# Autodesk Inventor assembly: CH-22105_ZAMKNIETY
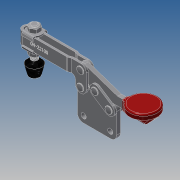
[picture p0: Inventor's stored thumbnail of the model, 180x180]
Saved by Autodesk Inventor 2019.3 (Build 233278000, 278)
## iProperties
Company: Microsoft
Created: 2017-06
Part Number: CH-22105_ZAMKNIETY
Material: Ogólny
Description: STEP AP203
Document SubType Name: Assembly
Designer: CADENGINEERING4
Sending System: SolidWorks 2015
Preprocessor: SwSTEP 2.0
Title: CH-22105.STEP
Author: Windows
Revision Number: ÈÎºÎ
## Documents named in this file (9)
- E:\STRONA\Horizontal toggle clamp\CH-22105\CH-22105_ZAMKNIETY.iam
- E:\STRONA\Horizontal toggle clamp\CH-22105\22105-01.ipt
- E:\STRONA\Horizontal toggle clamp\CH-22105\14134.ipt
- E:\STRONA\Horizontal toggle clamp\CH-22105\14134-02.ipt
- E:\STRONA\Horizontal toggle clamp\CH-22105\22105-02.ipt
- E:\STRONA\Horizontal toggle clamp\CH-22105\22105-03.ipt
- E:\STRONA\Horizontal toggle clamp\CH-22105\22105-04.ipt
- E:\STRONA\Horizontal toggle clamp\CH-22105\FW140.ipt
- E:\STRONA\Horizontal toggle clamp\CH-22105\22105-05.ipt
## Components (14 placed, 14 different names)
1. 22105-01_1
2. 14134_2
3. 14134-02_3
4. 22105-02_4
5. 22105-03_5
6. 22105-04_6
7. FW140_7
8. 22105-04_8
9. FW140_9
10. 14134-02_10
11. 22105-05_11
12. 22105-05_12
13. 22105-05_13
14. 22105-05_14
